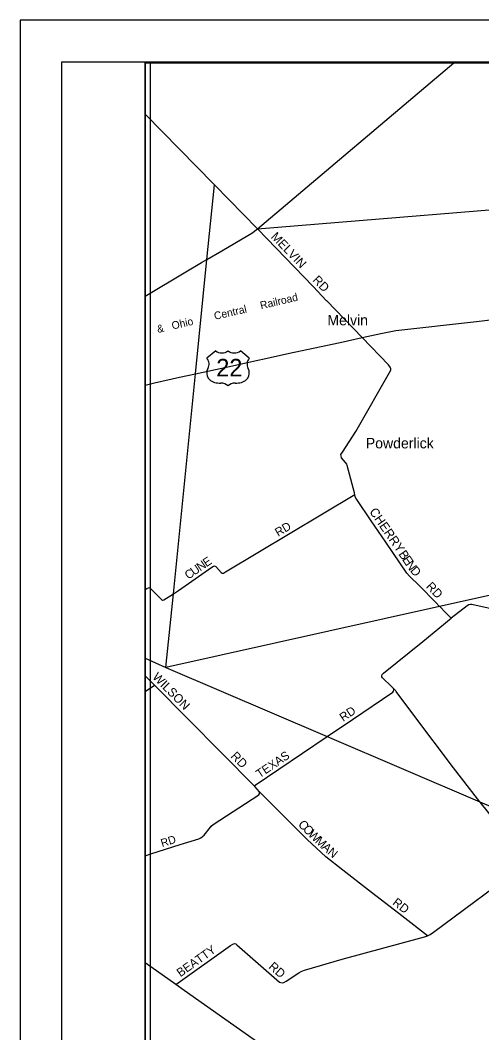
# Model space of a CAD drawing. Extents: x 0 to 784, y 0 to 440.
# Drawn here: x 0 to 111, y 196.7 to 440 of the extents above; entities that cross this region are included whole.
import ezdxf

# ---------------------------------------------------------------- set-up
doc = ezdxf.new("R2010")
doc.units = 0
for name, color, linetype in [('Default', 7, 'Continuous'), ('SH_Border', 7, 'Continuous'), ('SH_Cut_Line', 7, 'Continuous')]:
    doc.layers.add(name, color=color, linetype=linetype)

msp = doc.modelspace()

# ---------------------------------------------------------------- linework, layer by layer
at = {"layer": 'Default'}
for p, q in [((30.04, 429.76), (30.04, 417.42)), ((178.64, 429.76), (30.04, 429.76)), ((30.04, 417.42), (30.04, 286.69)), ((46.99, 360.55), (44.87, 358.79)), ((55.05, 358.79), (52.93, 360.55)), ((47.84, 352.81), (48.26, 352.81)), ((51.66, 352.81), (52.08, 352.81))]:
    msp.add_line(p, q, dxfattribs=at)
for points in [[(30.04, 417.42), (46.56, 400.57), (46.68, 400.45), (57.02, 389.91), (139.18, 396.63), (151.04, 406.68), (178.64, 429.76)], [(30.04, 429.76), (356.24, 429.76)], [(30.04, 429.76), (356.24, 429.76)], [(30.04, 429.76), (356.24, 429.76)], [(57.02, 389.91), (104.22, 429.76)], [(30.04, 286.69), (35.04, 284.49), (36.82, 302.17), (42.12, 355.05), (44.88, 382.52), (46.68, 400.45), (46.56, 400.57), (30.04, 417.42)], [(46.56, 400.58), (30.04, 417.42)], [(57.02, 389.91), (46.68, 400.45), (46.56, 400.57), (46.56, 400.58)], [(44.83, 382.49), (44.88, 382.52), (48.44, 384.62), (54.72, 388.25), (55.69, 388.87), (57.02, 389.91)], [(73.72, 372.57), (73.67, 372.61), (70.4, 376.01), (57.02, 389.91)], [(30.04, 373.66), (39.84, 379.54), (43.57, 381.75), (44.83, 382.49)], [(82.24, 363.72), (82.24, 363.72), (73.72, 372.57)], [(30.04, 352.34), (32.29, 352.89), (38.27, 354.22), (42.12, 355.05), (49.88, 356.74), (65.85, 360.21), (76.94, 362.53), (82.24, 363.72), (86.73, 364.73), (89.1, 365.22), (90.27, 365.43), (109.7, 367.64), (125.69, 369.54)], [(80.37, 326.31), (80.35, 326.39), (78.59, 333.02), (78.5, 333.33), (78.19, 333.69), (77.28, 334.84), (77.14, 335.29), (77.12, 335.64), (77.46, 336.17), (80.72, 341.16), (89.08, 355.88), (89.1, 356.2), (88.97, 356.64), (88.52, 357.22), (82.24, 363.72)], [(100.95, 299.01), (100.83, 299.13), (99.9, 300.07), (96.01, 304.1), (93.57, 306.42), (92.98, 307.14), (87.88, 314.61), (84.36, 319.68), (80.91, 324.82), (80.72, 325.16), (80.57, 325.54), (80.45, 325.99), (80.37, 326.31)], [(38.02, 302.96), (38.05, 302.99), (46.06, 308.54), (46.44, 308.81), (46.72, 308.86), (47.01, 308.73), (48.32, 307.32), (48.52, 307.14), (48.85, 307.14), (49.33, 307.47), (80.45, 325.99)], [(177.35, 316.06), (100.83, 299.13), (35.04, 284.49), (73.81, 267.89), (110.52, 252.18), (116.33, 249.66), (125.29, 245.78), (143.28, 224.29), (163.94, 199.83), (177.25, 183.75)], [(30.04, 303.16), (30.45, 303.43), (30.83, 303.63), (31.07, 303.66), (31.44, 303.35), (33.99, 300.8), (34.2, 300.62), (34.52, 300.73), (36.82, 302.17), (38.02, 302.96)], [(115.42, 298.11), (108.58, 299.61), (108.27, 299.63), (107.88, 299.55), (107.43, 299.3), (103.63, 296.28)], [(103.63, 296.28), (102.16, 297.78), (100.95, 299.01)], [(73.57, 267.73), (73.6, 267.75), (73.81, 267.89), (79.85, 271.97), (89.61, 278.56), (89.76, 278.79), (89.81, 279.05), (89.78, 279.4), (89.25, 279.87), (87.14, 281.95), (86.96, 282.2), (86.95, 282.43), (87.05, 282.75), (87.37, 283.12), (96.77, 290.67), (103.63, 296.28)], [(30.04, 286.69), (35.04, 284.49), (73.81, 267.89), (110.52, 252.18), (116.33, 249.66), (125.29, 245.78), (143.28, 224.29), (163.94, 199.83), (173.81, 187.91)], [(56.42, 255.82), (32.27, 280.2), (30.04, 282.45)], [(30.04, 278.7), (32.27, 280.2)], [(110.93, 251.68), (110.52, 252.18), (109.97, 252.86), (104.17, 260.33), (94.64, 272.97), (90.41, 278.67), (90.29, 278.81), (89.78, 279.4)], [(56.43, 256.13), (56.49, 256.19), (73.57, 267.73)], [(57.55, 254.61), (56.42, 255.82), (56.38, 256), (56.42, 256.12), (56.43, 256.13)], [(30.04, 239.21), (31.39, 239.67), (38.47, 241.89), (42.94, 243.3), (43.44, 243.51), (44.19, 244.16), (45.71, 246.11), (45.88, 246.32), (46.39, 246.69), (57.36, 253.82), (57.5, 254.09), (57.55, 254.39), (57.55, 254.61)], [(83.74, 230.95), (77.55, 235.74), (73.46, 238.94), (69.01, 243.09), (57.55, 254.61)], [(142.81, 223.95), (137.94, 220.32), (134.58, 223.45), (130.95, 226.88), (130, 227.77), (129.14, 228.76), (121.63, 237.42), (113.98, 247.9), (110.93, 251.67), (110.93, 251.68)], [(37.41, 208.3), (50.57, 217.66), (51.09, 217.97), (51.51, 218.1), (51.8, 218.03), (52.07, 217.84), (62.32, 208.86), (62.68, 208.72), (63, 208.66), (63.4, 208.73), (63.98, 209.05), (67, 211.08), (67.57, 211.42), (68.37, 211.73), (77.38, 214.33), (97.17, 219.74), (97.94, 219.99), (98.56, 220.26), (99.4, 220.86), (121.42, 237.2), (121.63, 237.42)], [(97.94, 219.99), (91.73, 224.78), (83.75, 230.95), (83.74, 230.95)], [(37.41, 208.3), (30.04, 213.5)], [(134.84, 147.23), (129.05, 147.63), (128.52, 147.72), (128.27, 147.8), (126.92, 148.37), (114.76, 156.37), (95.69, 168.8), (88.72, 173.31), (75.89, 181.87), (59, 193.09), (39.44, 206.81), (37.41, 208.3)]]:
    msp.add_lwpolyline(points, dxfattribs=at)
msp.add_lwpolyline([(31.33, 429.99), (465.77, 429.99), (465.77, 10.05), (31.33, 10.05)], close=True, dxfattribs=at)
for centre, major_axis, start_param, end_param in [((48.47, 361.8), (2.12, 0), 3.936991, 5.487786), ((51.45, 361.8), (2.12, 0), 3.936991, 5.487786), ((42.43, 357.38), (2.97, 0), 5.838949, 6.894067), ((57.49, 357.38), (-2.97, 0), 5.672304, 6.727422), ((47.8, 355.27), (2.97, 0), 2.702327, 4.723529), ((52.11, 355.27), (2.97, 0), 4.701249, 6.722451), ((48.26, 351.06), (-2.12, 0), 3.785094, 4.712389), ((51.66, 351.06), (-2.12, 0), 4.712389, 5.639684)]:
    msp.add_ellipse(centre, major_axis=major_axis, ratio=0.82844, start_param=start_param, end_param=end_param, dxfattribs=at)
at = {"layer": 'SH_Border'}
for points in [[(10, 430), (30, 430), (30, 10), (10, 10)], [(30, 430), (670, 430), (670, 10), (30, 10)]]:
    msp.add_lwpolyline(points, close=True, dxfattribs=at)
at = {"layer": 'SH_Cut_Line'}
msp.add_lwpolyline([(0, 0), (680, 0), (680, 440), (0, 440)], close=True, dxfattribs=at)

# ---------------------------------------------------------------- texts
at = {"layer": 'Default'}
for s, height, rotation, p in [('MELVIN', 2.126, 313.943, (60.13, 387.84)), ('RD', 2.126, 314.0807, (70.15, 377.43)), ('Railroad', 1.856, 13.3506, (57.91, 370.52)), ('Central', 1.852, 12.8876, (46.82, 367.99)), ('Ohio', 1.852, 12.8669, (36.64, 365.67)), ('Melvin', 2.525, 0, (73.86, 366.68)), ('&', 1.85, 13.0834, (33.1, 364.84)), ('Powderlick', 2.525, 0, (83.1, 337.11)), ('CHERRY', 2.167, 304.6427, (83.84, 321.91)), ('RD', 2.016, 30.935, (62.01, 315.86)), ('B', 2.17, 304.0479, (90.85, 311.71)), ('U', 2.05, 34.8679, (41.8, 306.49)), ('N', 2.05, 34.8582, (43.28, 307.52)), ('E', 2.04, 33.3615, (44.75, 308.54)), ('E', 2.17, 304.0414, (91.73, 310.41)), ('N', 2.17, 304.2193, (92.53, 309.22)), ('C', 2.05, 34.8719, (40.42, 305.53)), ('D', 2.14, 311.3533, (93.63, 307.63)), ('RD', 2.126, 314.0801, (97.43, 303.78)), ('WILSON', 2.122, 314.7064, (31.63, 282)), ('RD', 2.045, 34.263, (77.64, 271.37)), ('RD', 2.122, 314.7162, (50.46, 262.98)), ('TEXAS', 2.043, 34.1012, (57.56, 257.8)), ('C', 2.12, 314.5548, (66.66, 246.58)), ('O', 2.12, 314.6902, (67.8, 245.42)), ('RD', 1.9, 17.7036, (34.13, 241.27)), ('W', 2.11, 316.0725, (69.06, 244.15)), ('M', 2.11, 317.0747, (70.75, 242.52)), ('A', 2.11, 317.4368, (72.34, 241.04)), ('N', 2.08, 320.7057, (73.73, 239.77)), ('RD', 2.071, 322.4079, (89.34, 227.61)), ('BEATTY', 2.053, 35.3422, (38.52, 210)), ('RD', 2.098, 318.6237, (59.57, 212.32))]:
    msp.add_text(s, height=height, rotation=rotation, dxfattribs=at).set_placement(p)
msp.add_text('22', height=4.219, dxfattribs=at).set_placement((47.14, 354.4))

doc.saveas('drawing.dxf')
